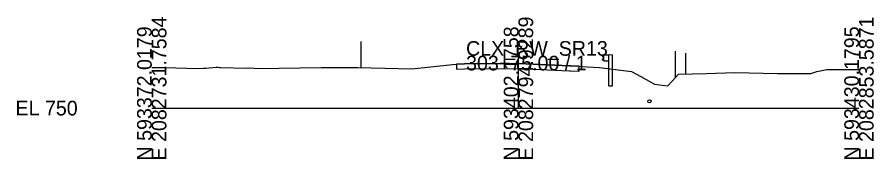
# Model space of a CAD drawing. Extents: x -26 to 2138, y -10 to 4518.
# Drawn here: x 974.3 to 1137.8, y 3490.3 to 3517.4 of the extents above; entities that cross this region are included whole.
import ezdxf

# ---------------------------------------------------------------- set-up
doc = ezdxf.new("R2010")
doc.units = 0
for name, color, linetype in [('GK_Cells', 7, 'Continuous'), ('MD_X_Asphalt_Pavement', 7, 'Continuous'), ('RD_P_Cells', 7, 'Continuous'), ('RW_P_Esmt_SH', 7, 'Continuous'), ('RW_X_Esmt_SH', 7, 'Continuous'), ('UT_X_Water', 7, 'Continuous'), ('XS_X_Ground_Line', 7, 'Continuous')]:
    doc.layers.add(name, color=color, linetype=linetype)

msp = doc.modelspace()

# ---------------------------------------------------------------- linework, layer by layer
at = {"layer": 'GK_Cells'}
for p, q in [((1070, 3500), (1070, 3510)), ((1000, 3500), (1070, 3500)), ((1070, 3500), (1135, 3500))]:
    msp.add_line(p, q, dxfattribs=at)
at = {"layer": 'MD_X_Asphalt_Pavement'}
msp.add_lwpolyline([(1059.7, 3508.47), (1058.19, 3508.42), (1058.19, 3507.46), (1059.7, 3507.52), (1059.71, 3507.52), (1059.73, 3507.52), (1070.03, 3507.54), (1079.74, 3507.13), (1079.95, 3507.12), (1081.55, 3507.03), (1081.56, 3507.03), (1081.56, 3507.99), (1081.55, 3507.99), (1079.95, 3508.08), (1079.74, 3508.09), (1070.03, 3508.5), (1059.73, 3508.47), (1059.71, 3508.47), (1059.7, 3508.47)], dxfattribs=at)
at = {"layer": 'RD_P_Cells'}
for p, q in [((1086.03, 3509.98), (1086.19, 3510.09)), ((1086.24, 3509.7), (1086.03, 3509.85)), ((1086.03, 3509.34), (1086.24, 3509.48)), ((1086.19, 3510.09), (1086.28, 3510.1)), ((1086.27, 3509.59), (1086.27, 3509.64)), ((1086.27, 3509.55), (1086.27, 3509.59)), ((1086.28, 3509), (1086.28, 3510.19)), ((1086.28, 3510.19), (1087.28, 3510.19)), ((1087.28, 3510.19), (1087.36, 3510.23)), ((1087.28, 3504.23), (1087.28, 3510.19)), ((1087.36, 3510.23), (1087.9, 3510.15)), ((1087.9, 3510.15), (1087.95, 3510.13)), ((1087.95, 3504.23), (1087.95, 3510.13)), ((1086.19, 3509.1), (1086.03, 3509.21)), ((1086.28, 3509.08), (1086.19, 3509.1)), ((1086.28, 3509), (1087.28, 3509)), ((1087.28, 3504.23), (1087.95, 3504.23))]:
    msp.add_line(p, q, dxfattribs=at)
for points in [[(1086.26, 3509.62), (1086.26, 3509.56), (1086.24, 3509.56), (1086.24, 3509.62)], [(1086.26, 3509.65), (1086.26, 3509.53), (1086.27, 3509.53), (1086.27, 3509.65)]]:
    msp.add_lwpolyline(points, close=True, dxfattribs=at)
for centre, start, end in [((1086.08, 3509.91), 125.2323, 235.038), ((1086.19, 3509.64), 0, 55.038), ((1086.19, 3509.55), 304.962, 0), ((1086.08, 3509.28), 125.2323, 235.038)]:
    msp.add_arc(centre, 0.0781, start, end, dxfattribs=at)
at = {"layer": 'RW_P_Esmt_SH'}
msp.add_line((1101.98, 3506.52), (1101.98, 3510.52), dxfattribs=at)
at = {"layer": 'RW_X_Esmt_SH'}
for p, q in [((1040, 3507.75), (1040, 3512.75)), ((1100, 3505.86), (1100, 3510.86))]:
    msp.add_line(p, q, dxfattribs=at)
at = {"layer": 'UT_X_Water'}
msp.add_circle((1095, 3501.31), 0.3, dxfattribs=at)
at = {"layer": 'XS_X_Ground_Line'}
msp.add_lwpolyline([(1000, 3507.78), (1002.45, 3507.73), (1008.85, 3507.58), (1009.83, 3507.61), (1010.32, 3507.63), (1012.3, 3507.81), (1012.4, 3507.81), (1012.64, 3507.79), (1012.7, 3507.79), (1012.97, 3507.77), (1012.99, 3507.77), (1013, 3507.77), (1013.06, 3507.76), (1013.09, 3507.76), (1013.12, 3507.76), (1018, 3507.61), (1018.62, 3507.69), (1018.64, 3507.69), (1020.3, 3507.59), (1032.36, 3507.78), (1039.32, 3507.77), (1049.64, 3507.48), (1057.4, 3508.31), (1058.15, 3508.41), (1058.19, 3508.42), (1059.7, 3508.47), (1059.71, 3508.47), (1059.73, 3508.47), (1070.03, 3508.5), (1079.74, 3508.09), (1079.95, 3508.08), (1081.55, 3507.99), (1081.56, 3507.99), (1081.96, 3507.95), (1085.45, 3507.76), (1091.58, 3506.97), (1093.33, 3506.02), (1095.98, 3504.57), (1097.43, 3504.35), (1098.53, 3504.27), (1099.37, 3505.14), (1100.54, 3506.48), (1105.91, 3506.62), (1111.33, 3506.8), (1119.46, 3506.64), (1120.4, 3506.64), (1121.08, 3506.64), (1121.72, 3506.64), (1123.79, 3506.64), (1125.83, 3506.64), (1126.93, 3506.97), (1128.85, 3507.38), (1135, 3507.38)], dxfattribs=at)

# ---------------------------------------------------------------- texts
msp.add_text('-', height=0.0001).set_placement((1000, 3500))
at = {"layer": 'GK_Cells'}
for s, p in [('E 2082731.7584', (1002.8, 3490)), ('E 2082794.9289', (1072.8, 3490)), ('E 2082853.5871', (1137.8, 3490)), ('N 593372.0179', (1000, 3490)), ('N 593402.1758', (1070, 3490)), ('N 593430.1795', (1135, 3490))]:
    msp.add_text(s, height=2.8, rotation=90, dxfattribs=at).set_placement(p)
for s, p in [('CLX_RW_SR13', (1060, 3510)), ('303+75.00 / 1', (1060, 3507.2)), ('EL 750', (974, 3498.6))]:
    msp.add_text(s, height=2.8, dxfattribs=at).set_placement(p)

doc.saveas('drawing.dxf')
